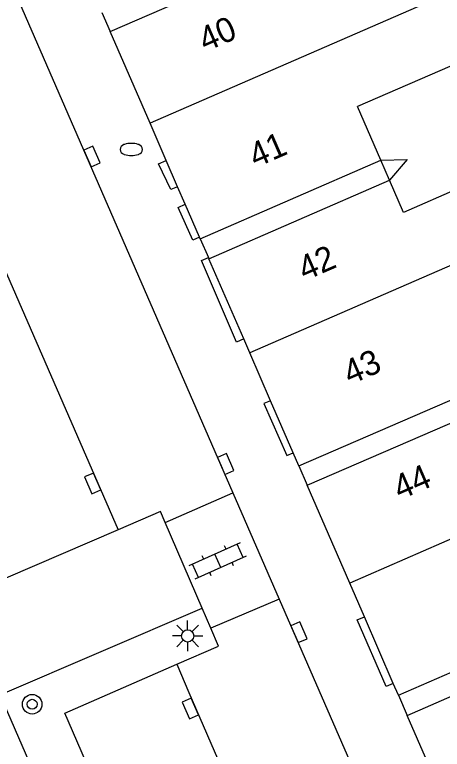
# Model space of a CAD drawing. Extents: x 132998 to 136004, y 396998 to 398512.
# Drawn here: x 133217.85 to 133235.3, y 397132.9 to 397162.85 of the extents above; entities that cross this region are included whole.
import ezdxf

# ---------------------------------------------------------------- set-up
doc = ezdxf.new("R2010")
doc.units = 0
for name, color, linetype in [('gg-afsc-erfafscheiding', 7, 'Continuous'), ('gg-anno-huisnummerreeks BGT', 7, 'Continuous'), ('gg-bbg-gedigitaliseerde bebouwing', 7, 'Continuous'), ('gg-bbg-gedigitaliseerde bebouwing onder overbouw', 7, 'Continuous'), ('gg-bbg-gedigitaliseerde overbouw', 7, 'Continuous'), ('gg-bbg-hoofdgebouw', 7, 'Continuous'), ('gg-bbg-pand overbouw', 7, 'Continuous'), ('gg-bbg-tussenscheiding', 7, 'Continuous'), ('gg-knt-verharding', 7, 'Continuous'), ('gg-knt-verharding nz', 7, 'Continuous'), ('gt-symb-boom', 7, 'Continuous'), ('gt-symb-brandkraan', 7, 'Continuous'), ('gt-symb-klinker verharding', 7, 'Continuous'), ('gt-symb-kolk', 7, 'Continuous'), ('gt-symb-lichtmast', 7, 'Continuous')]:
    doc.layers.add(name, color=color, linetype=linetype)

# ---------------------------------------------------------------- blocks, each defined once
blk = doc.blocks.new('gt0-LMAST')
at = {"layer": 'gt-symb-lichtmast'}
for p, q in [((-0.005, 0.246), (-0.005, 0.621)), ((-0.182, 0.173), (-0.447, 0.438)), ((0.172, 0.173), (0.437, 0.438)), ((-0.255, -0.004), (-0.63, -0.004)), ((-0.182, -0.181), (-0.447, -0.446)), ((-0.005, -0.254), (-0.005, -0.629)), ((0.437, -0.446), (0.172, -0.181)), ((0.245, -0.004), (0.62, -0.004))]:
    blk.add_line(p, q, dxfattribs=at)
blk.add_circle((-0.005, -0.004), 0.25, dxfattribs=at)
blk = doc.blocks.new('gt0-KOLK')
at = {"layer": 'gt-symb-kolk'}
blk.add_lwpolyline([(0, 0), (0.375, 0), (0.375, 0.4), (-0.375, 0.4), (-0.375, 0), (0, 0)], dxfattribs=at)
blk = doc.blocks.new('gt0-KL1')
at = {"layer": 'gt-symb-klinker verharding'}
for p, q in [((-1.15, 0.3), (1.15, 0.3)), ((-1, -0.3), (-1, 0.3)), ((-0.5, 0.3), (-0.5, 0.45)), ((0, -0.3), (0, 0.3)), ((0.5, 0.3), (0.5, 0.45)), ((1, -0.3), (1, 0.3)), ((-1.15, -0.3), (1.15, -0.3)), ((-0.5, -0.45), (-0.5, -0.3)), ((0.5, -0.45), (0.5, -0.3))]:
    blk.add_line(p, q, dxfattribs=at)
blk = doc.blocks.new('gt0-BR')
at = {"layer": 'gt-symb-brandkraan'}
for centre, radius, start, end in [((-0.244, 0), 0.206, 107.5669, 252.4331), ((0.599, -2.664), 3, 106.892, 107.5669), ((0, -0.691), 0.938, 73.108, 106.892), ((-0.599, -2.664), 3, 72.4331, 73.108), ((0.244, 0), 0.206, 287.567, 72.4331), ((0.599, 2.664), 3, 252.4331, 253.108), ((0, 0.691), 0.938, 253.108, 286.8921), ((-0.599, 2.664), 3, 286.8921, 287.567)]:
    blk.add_arc(centre, radius, start, end, dxfattribs=at)
blk = doc.blocks.new('gt0-BOOM')
at = {"layer": 'gt-symb-boom'}
for radius in [0.4, 0.2]:
    blk.add_circle((0, 0), radius, dxfattribs=at)

msp = doc.modelspace()

# ---------------------------------------------------------------- linework, layer by layer
at = {"layer": 'gg-afsc-erfafscheiding'}
msp.add_lwpolyline([(133232.791, 397156.918), (133233.862, 397156.946), (133233.145, 397156.102)], dxfattribs=at)
at = {"layer": 'gg-bbg-gedigitaliseerde bebouwing'}
for p, q in [((133239.626, 397162.493), (133231.838, 397159.108)), ((133232.791, 397156.918), (133231.838, 397159.108)), ((133241.317, 397158.098), (133233.716, 397154.791)), ((133233.716, 397154.791), (133233.145, 397156.102))]:
    msp.add_line(p, q, dxfattribs=at)
at = {"layer": 'gg-bbg-gedigitaliseerde bebouwing onder overbouw'}
for p, q in [((133221.748, 397162.162), (133229.1, 397165.358)), ((133225.42, 397153.714), (133232.791, 397156.918)), ((133225.774, 397152.898), (133233.145, 397156.102)), ((133229.447, 397144.45), (133236.894, 397147.687)), ((133229.79, 397143.661), (133237.237, 397146.898)), ((133233.511, 397135.101), (133240.949, 397138.334)), ((133233.868, 397134.28), (133241.305, 397137.513))]:
    msp.add_line(p, q, dxfattribs=at)
at = {"layer": 'gg-bbg-gedigitaliseerde overbouw'}
msp.add_line((133233.145, 397156.102), (133232.791, 397156.918), dxfattribs=at)
at = {"layer": 'gg-bbg-hoofdgebouw'}
for p, q in [((133223.372, 397158.426), (133221.748, 397162.162)), ((133224.032, 397156.907), (133223.372, 397158.426)), ((133224.498, 397155.836), (133224.032, 397156.907)), ((133224.809, 397155.119), (133224.498, 397155.836)), ((133225.394, 397153.775), (133224.809, 397155.119)), ((133225.42, 397153.714), (133225.394, 397153.775)), ((133227.194, 397149.632), (133225.774, 397152.898)), ((133227.442, 397149.062), (133227.194, 397149.632)), ((133228.292, 397147.108), (133227.442, 397149.062)), ((133229.215, 397144.985), (133228.292, 397147.108)), ((133229.447, 397144.45), (133229.215, 397144.985)), ((133231.522, 397139.678), (133229.79, 397143.661)), ((133232.12, 397138.302), (133231.522, 397139.678)), ((133233.3, 397135.587), (133232.12, 397138.302)), ((133233.511, 397135.101), (133233.3, 397135.587)), ((133234.707, 397132.351), (133233.868, 397134.28))]:
    msp.add_line(p, q, dxfattribs=at)
at = {"layer": 'gg-bbg-pand overbouw'}
for p, q in [((133221.41, 397162.939), (133221.748, 397162.162)), ((133225.42, 397153.714), (133225.752, 397152.949)), ((133225.752, 397152.949), (133225.774, 397152.898)), ((133229.447, 397144.45), (133229.79, 397143.661)), ((133233.511, 397135.101), (133233.868, 397134.28))]:
    msp.add_line(p, q, dxfattribs=at)
at = {"layer": 'gg-bbg-tussenscheiding'}
for p, q in [((133238.49, 397164.998), (133223.372, 397158.426)), ((133242.413, 397155.576), (133227.442, 397149.062)), ((133244.974, 397145.526), (133231.522, 397139.678))]:
    msp.add_line(p, q, dxfattribs=at)
at = {"layer": 'gg-knt-verharding'}
for p, q in [((133223.994, 397142.143), (133226.755, 397143.354)), ((133226.755, 397143.354), (133228.644, 397139.023)), ((133225.498, 397138.652), (133223.994, 397142.143)), ((133222.074, 397141.852), (133217.493, 397139.873)), ((133228.644, 397139.023), (133225.853, 397137.831)), ((133225.853, 397137.831), (133225.498, 397138.652))]:
    msp.add_line(p, q, dxfattribs=at)
for points in [[(133211.956, 397172.754), (133214.358, 397167.234), (133216.02, 397167.97), (133226.755, 397143.354)], [(133224.498, 397155.836), (133224.225, 397155.718), (133223.719, 397156.771), (133224.032, 397156.907)], [(133225.394, 397153.775), (133225.116, 397153.654), (133224.524, 397154.995), (133224.809, 397155.119)], [(133227.194, 397149.632), (133226.895, 397149.502), (133225.478, 397152.83), (133225.752, 397152.949)], [(133228.292, 397147.108), (133228.021, 397146.993), (133228.954, 397144.872), (133229.215, 397144.985)], [(133223.994, 397142.143), (133223.798, 397142.597), (133222.074, 397141.852)], [(133228.644, 397139.023), (133239.47, 397114.2), (133237.81, 397113.518), (133239.796, 397108.824), (133241.45, 397109.63)], [(133228.421, 397109.42), (133217.261, 397135.12), (133225.498, 397138.652)], [(133233.3, 397135.587), (133233.011, 397135.462), (133231.831, 397138.176), (133232.12, 397138.302)], [(133224.471, 397136.365), (133226.167, 397137.103), (133225.853, 397137.831)], [(133230.334, 397110.327), (133219.893, 397134.373), (133224.471, 397136.365)]]:
    msp.add_lwpolyline(points, dxfattribs=at)
at = {"layer": 'gg-knt-verharding nz'}
for points in [[(133211.616, 397165.832), (133211.877, 397165.185), (133212.23, 397164.405), (133216.207, 397155.262), (133222.074, 397141.852)], [(133224.471, 397136.365), (133224.955, 397135.211), (133233.853, 397114.745), (133234.939, 397112.319)]]:
    msp.add_lwpolyline(points, dxfattribs=at)

# ---------------------------------------------------------------- block references
at = {"layer": 'gt-symb-boom'}
msp.add_blockref('gt0-BOOM', (133218.562, 397134.735), dxfattribs=at)
at = {"layer": 'gt-symb-brandkraan'}
msp.add_blockref('gt0-BR', (133222.609, 397157.355), dxfattribs=at)
at = {"layer": 'gt-symb-klinker verharding', "rotation": 24.078837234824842}
msp.add_blockref('gt0-KL1', (133226.142, 397140.585), dxfattribs=at)
at = {"layer": 'gt-symb-kolk'}
for p, rotation in [((133220.826, 397156.989), -66.53799977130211), ((133226.278, 397144.449), -66.48544331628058), ((133221.213, 397143.819), 113.64250165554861), ((133229.268, 397137.592), -66.41000982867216), ((133225.205, 397134.642), 113.69497103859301)]:
    msp.add_blockref('gt0-KOLK', p, dxfattribs=dict(at, rotation=rotation))
at = {"layer": 'gt-symb-lichtmast'}
msp.add_blockref('gt0-LMAST', (133224.913, 397137.522), dxfattribs=at)

# ---------------------------------------------------------------- texts
at = {"layer": 'gg-anno-huisnummerreeks BGT'}
for s, p in [('40', (133225.628, 397161.32)), ('41', (133227.681, 397156.596)), ('42', (133229.686, 397151.983)), ('43', (133231.53, 397147.742)), ('44', (133233.57, 397143.05))]:
    msp.add_text(s, height=1, rotation=23.5, dxfattribs=at).set_placement(p)

doc.saveas('drawing.dxf')
